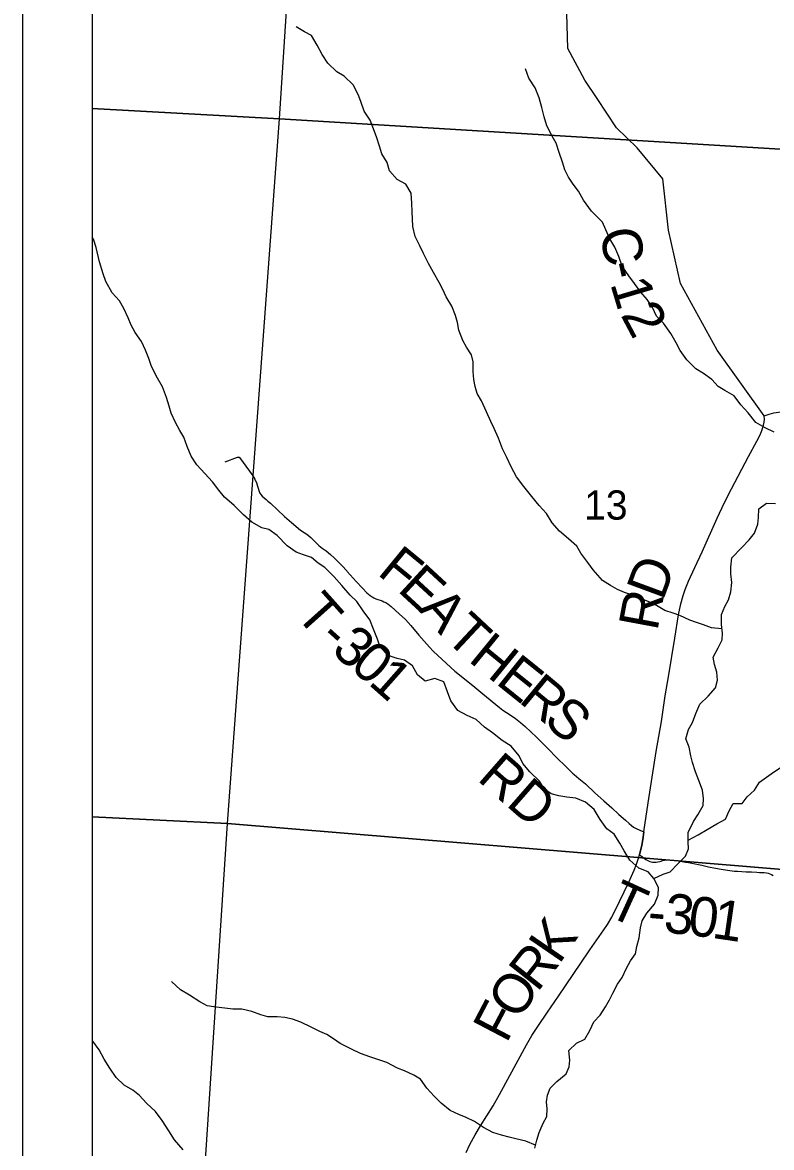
# Model space of a CAD drawing. Extents: x 0 to 34, y 0 to 22.
# Drawn here: x 2 to 3.074, y 15.5 to 17.112 of the extents above; entities that cross this region are included whole.
import ezdxf

# ---------------------------------------------------------------- set-up
doc = ezdxf.new("R2010")
doc.units = 0
for name, color, linetype in [('GM_X_Corporation', 7, 'Continuous'), ('GM_X_County_Road', 7, 'Continuous'), ('GM_X_County_Road_Text', 7, 'Continuous'), ('GM_X_Major_River', 7, 'Continuous'), ('GM_X_Minor_River', 7, 'Continuous'), ('GM_X_Section_Text', 7, 'Continuous'), ('GM_X_Township_Road', 7, 'Continuous'), ('GM_X_Township_Road_Text', 7, 'Continuous'), ('SH_Data', 7, 'Continuous')]:
    doc.layers.add(name, color=color, linetype=linetype)

msp = doc.modelspace()

# ---------------------------------------------------------------- linework, layer by layer
at = {"layer": 'GM_X_Corporation'}
for points in [[(2.1, 19.0816), (2.1, 14.1), (3.1902, 14.1), (3.1919, 14.1255), (3.2339, 14.7735), (3.2844, 15.554), (3.3059, 15.8844), (3.3516, 16.5898), (3.3951, 17.2616), (3.507, 18.9883), (2.9513, 19.0267), (2.509, 19.0572), (2.4972, 19.0545), (2.4649, 19.0567)], [(2.1, 18.0323), (2.1, 16.9887), (2.3682, 16.9741), (2.436, 18.0137)], [(2.436, 18.0137), (3.4457, 17.9455), (3.3779, 16.9127), (2.3682, 16.9741)], [(2.1, 16.9887), (2.1, 15.9736), (2.2939, 15.964), (2.3682, 16.9741)], [(3.3779, 16.9127), (3.31, 15.8916), (3.3089, 15.8803), (2.2939, 15.964), (2.3682, 16.9741)], [(2.1, 15.9736), (2.1, 14.9482), (2.2272, 14.9411), (2.2939, 15.964)], [(2.2939, 15.964), (3.3089, 15.8803), (3.2437, 14.8797), (2.2272, 14.9411)]]:
    msp.add_lwpolyline(points, close=True, dxfattribs=at)
at = {"layer": 'GM_X_County_Road'}
for points in [[(3.0632, 16.5485), (2.996, 16.6425), (2.9433, 16.738), (2.926, 16.8142), (2.9178, 16.8878), (2.8812, 16.9325), (2.8515, 16.9612), (2.8237, 17.0029), (2.8062, 17.0294), (2.7818, 17.0745), (2.777, 17.2417)], [(3.0632, 16.5485), (3.0704, 16.5509), (3.077, 16.5524), (3.0838, 16.5537), (3.0931, 16.5548), (3.1025, 16.5553), (3.1119, 16.5551), (3.1274, 16.5537), (3.1459, 16.552), (3.1583, 16.5514), (3.1706, 16.5515), (3.186, 16.5523), (3.2138, 16.5548), (3.2694, 16.5609), (3.2847, 16.5631), (3.2938, 16.5648), (3.3027, 16.5672), (3.3085, 16.5693), (3.3226, 16.5756), (3.3563, 16.5915), (3.3576, 16.592), (3.363, 16.5943)], [(2.8907, 15.9522), (2.8967, 15.9938), (2.9084, 16.0673), (2.9158, 16.1102), (2.9215, 16.147), (2.9262, 16.1745), (2.935, 16.2297), (2.9406, 16.2634), (2.9438, 16.2787), (2.947, 16.2907), (2.95, 16.2996), (2.9546, 16.3112), (2.9637, 16.3309), (2.9744, 16.3533), (2.9959, 16.4015), (3.0065, 16.424), (3.0162, 16.4435), (3.0408, 16.4901), (3.0529, 16.5118), (3.057, 16.52), (3.0595, 16.5257), (3.0615, 16.5314), (3.0623, 16.5347), (3.0632, 16.539), (3.0635, 16.5436), (3.0632, 16.5485)], [(2.8844, 15.9194), (2.8856, 15.9235), (2.8876, 15.9326), (2.8897, 15.9447), (2.8907, 15.9522)], [(2.636, 15.4929), (2.6413, 15.5042), (2.6487, 15.518), (2.6566, 15.5312), (2.6747, 15.5598), (2.6839, 15.5759), (2.7224, 15.6468), (2.7302, 15.6603), (2.7385, 15.6734), (2.7525, 15.694), (2.7685, 15.7169), (2.8112, 15.7801), (2.8133, 15.7832), (2.8335, 15.8116), (2.8386, 15.8193), (2.8446, 15.8301), (2.8557, 15.8523), (2.869, 15.8803), (2.8766, 15.8973), (2.8801, 15.9059), (2.8831, 15.9146), (2.8844, 15.9194)]]:
    msp.add_lwpolyline(points, dxfattribs=at)
at = {"layer": 'GM_X_Major_River'}
for points in [[(2.9647, 16.0382), (2.9605, 16.0514), (2.9582, 16.0613), (2.9555, 16.0734), (2.9509, 16.0855), (2.9547, 16.0988), (2.9603, 16.1087), (2.9652, 16.1216), (2.9708, 16.1352), (2.9829, 16.1467), (2.9934, 16.1588), (2.9961, 16.1695), (2.9953, 16.1808), (2.9918, 16.1922), (2.9899, 16.2024), (2.9974, 16.2157), (3.003, 16.2275), (3.0034, 16.2369), (3.0018, 16.2491), (3.0022, 16.2635), (3.007, 16.2749), (3.0119, 16.2847), (3.0153, 16.2961), (3.0168, 16.3094), (3.0156, 16.3219), (3.0155, 16.3314), (3.017, 16.3446), (3.0306, 16.3591), (3.0415, 16.3705), (3.0494, 16.38), (3.0539, 16.3933), (3.055, 16.4028), (3.0554, 16.4149), (3.0663, 16.4233), (3.0792, 16.4226)], [(2.7342, 15.499), (2.7372, 15.5104), (2.7406, 15.5214), (2.7466, 15.5347), (2.7515, 15.5442), (2.7522, 15.5552), (2.751, 15.5654), (2.7525, 15.5749), (2.7563, 15.5851), (2.7661, 15.5947), (2.7793, 15.6053), (2.7838, 15.6156), (2.7845, 15.6251), (2.7833, 15.6387), (2.7943, 15.6494), (2.806, 15.6551), (2.8135, 15.6676), (2.8191, 15.6798), (2.8282, 15.6897), (2.8357, 15.7015), (2.8414, 15.7117), (2.8462, 15.7212), (2.853, 15.7341), (2.8598, 15.7436), (2.8658, 15.7569), (2.8718, 15.7672), (2.8786, 15.7775), (2.8808, 15.7881), (2.8842, 15.8002), (2.886, 15.8146), (2.8883, 15.8245), (2.895, 15.8359), (2.906, 15.8488), (2.9112, 15.8617), (2.9116, 15.8723), (2.9051, 15.8856), (2.9183, 15.8917), (2.9285, 15.8948), (2.9394, 15.9066), (2.9504, 15.9176), (2.9549, 15.9279), (2.9541, 15.9381), (2.9544, 15.9514), (2.9619, 15.9669), (2.968, 15.9768), (2.9759, 15.9901), (2.9762, 16), (2.975, 16.0121), (2.9697, 16.0257), (2.9647, 16.0382)]]:
    msp.add_lwpolyline(points, dxfattribs=at)
at = {"layer": 'GM_X_Minor_River'}
for p, q in [((2.4043, 17.0987), (2.3925, 17.1055)), ((2.4145, 17.0931), (2.4043, 17.0987)), ((2.4225, 17.0795), (2.4145, 17.0931)), ((2.4294, 17.0662), (2.4225, 17.0795)), ((2.4377, 17.0538), (2.4294, 17.0662)), ((2.4506, 17.0413), (2.4377, 17.0538)), ((2.4613, 17.0349), (2.4506, 17.0413)), ((2.7258, 17.0323), (2.7209, 17.0456)), ((2.4742, 17.0228), (2.4613, 17.0349)), ((2.481, 17.0085), (2.4742, 17.0228)), ((2.735, 17.0183), (2.7258, 17.0323)), ((2.4852, 16.9986), (2.481, 17.0085)), ((2.7407, 17.004), (2.735, 17.0183)), ((2.4898, 16.985), (2.4852, 16.9986)), ((2.7445, 16.9903), (2.7407, 17.004)), ((2.7476, 16.9767), (2.7445, 16.9903)), ((2.4986, 16.9718), (2.4898, 16.985)), ((2.7518, 16.9638), (2.7476, 16.9767)), ((2.5024, 16.962), (2.4986, 16.9718)), ((2.5074, 16.948), (2.5024, 16.962)), ((2.7594, 16.9491), (2.7518, 16.9638)), ((2.512, 16.9347), (2.5074, 16.948)), ((2.7648, 16.9389), (2.7594, 16.9491)), ((2.515, 16.9237), (2.512, 16.9347)), ((2.7694, 16.9256), (2.7648, 16.9389)), ((2.5226, 16.9113), (2.515, 16.9237)), ((2.5261, 16.8995), (2.5226, 16.9113)), ((2.7739, 16.912), (2.7694, 16.9256)), ((2.7774, 16.901), (2.7739, 16.912)), ((2.5371, 16.8871), (2.5261, 16.8995)), ((2.7827, 16.8905), (2.7774, 16.901)), ((2.5496, 16.8803), (2.5371, 16.8871)), ((2.5572, 16.8675), (2.5496, 16.8803)), ((2.7896, 16.8802), (2.7827, 16.8905)), ((2.7968, 16.87), (2.7896, 16.8802)), ((2.558, 16.8531), (2.5572, 16.8675)), ((2.804, 16.8572), (2.7968, 16.87)), ((2.5588, 16.8406), (2.558, 16.8531)), ((2.8158, 16.8417), (2.804, 16.8572)), ((2.5593, 16.8307), (2.5588, 16.8406)), ((2.5597, 16.8197), (2.5593, 16.8307)), ((2.8314, 16.8259), (2.8158, 16.8417)), ((2.5631, 16.8053), (2.5597, 16.8197)), ((2.836, 16.8149), (2.8314, 16.8259)), ((2.8421, 16.8017), (2.836, 16.8149)), ((2.5696, 16.7917), (2.5631, 16.8053)), ((2.8493, 16.7899), (2.8421, 16.8017)), ((2.5746, 16.7811), (2.5696, 16.7917)), ((2.5822, 16.7668), (2.5746, 16.7811)), ((2.855, 16.7767), (2.8493, 16.7899)), ((2.589, 16.7535), (2.5822, 16.7668)), ((2.8596, 16.7627), (2.855, 16.7767)), ((2.5974, 16.7392), (2.589, 16.7535)), ((2.8691, 16.7487), (2.8596, 16.7627)), ((2.8775, 16.7378), (2.8691, 16.7487)), ((2.6024, 16.7293), (2.5974, 16.7392)), ((2.8866, 16.7257), (2.8775, 16.7378)), ((2.6073, 16.7187), (2.6024, 16.7293)), ((2.6153, 16.7055), (2.6073, 16.7187)), ((2.8954, 16.7151), (2.8866, 16.7257)), ((2.6207, 16.6923), (2.6153, 16.7055)), ((2.903, 16.7034), (2.8954, 16.7151)), ((2.9087, 16.6909), (2.903, 16.7034)), ((2.6234, 16.6821), (2.6207, 16.6923)), ((2.9189, 16.6811), (2.9087, 16.6909)), ((2.6257, 16.6711), (2.6234, 16.6821)), ((2.631, 16.6563), (2.6257, 16.6711)), ((2.9296, 16.6664), (2.9189, 16.6811)), ((2.6367, 16.6465), (2.631, 16.6563)), ((2.9368, 16.6531), (2.9296, 16.6664)), ((2.9429, 16.6418), (2.9368, 16.6531)), ((2.6436, 16.6355), (2.6367, 16.6465)), ((2.9521, 16.6286), (2.9429, 16.6418)), ((2.6459, 16.6257), (2.6436, 16.6355)), ((2.6459, 16.6117), (2.6459, 16.6257)), ((2.965, 16.6157), (2.9521, 16.6286)), ((2.6471, 16.6003), (2.6459, 16.6117)), ((2.9764, 16.609), (2.965, 16.6157)), ((2.9881, 16.6003), (2.9764, 16.609)), ((2.6487, 16.5905), (2.6471, 16.6003)), ((2.6517, 16.5802), (2.6487, 16.5905)), ((2.9972, 16.5901), (2.9881, 16.6003)), ((3.0067, 16.5845), (2.9972, 16.5901)), ((2.6582, 16.5697), (2.6517, 16.5802)), ((3.02, 16.577), (3.0067, 16.5845)), ((3.0299, 16.5641), (3.02, 16.577)), ((2.6651, 16.5538), (2.6582, 16.5697)), ((3.0401, 16.5524), (3.0299, 16.5641)), ((2.6712, 16.5402), (2.6651, 16.5538)), ((2.6761, 16.5303), (2.6712, 16.5402)), ((3.0512, 16.5388), (3.0401, 16.5524)), ((2.6822, 16.5163), (2.6761, 16.5303)), ((3.0644, 16.5309), (3.0512, 16.5388)), ((3.0777, 16.5249), (3.0644, 16.5309)), ((2.6883, 16.5012), (2.6822, 16.5163)), ((2.6944, 16.4887), (2.6883, 16.5012)), ((2.7005, 16.4751), (2.6944, 16.4887)), ((2.7082, 16.4607), (2.7005, 16.4751)), ((2.7188, 16.4471), (2.7082, 16.4607)), ((2.7302, 16.4328), (2.7188, 16.4471)), ((2.7405, 16.4199), (2.7302, 16.4328)), ((2.7511, 16.4082), (2.7405, 16.4199)), ((2.7591, 16.395), (2.7511, 16.4082)), ((2.7697, 16.3829), (2.7591, 16.395)), ((2.7826, 16.372), (2.7697, 16.3829)), ((2.7944, 16.3615), (2.7826, 16.372)), ((2.8005, 16.3516), (2.7944, 16.3615)), ((2.8104, 16.338), (2.8005, 16.3516)), ((2.818, 16.3278), (2.8104, 16.338)), ((2.8313, 16.3124), (2.818, 16.3278)), ((2.8431, 16.3052), (2.8313, 16.3124)), ((2.8529, 16.2996), (2.8431, 16.3052)), ((2.8631, 16.2951), (2.8529, 16.2996)), ((2.8764, 16.291), (2.8631, 16.2951)), ((2.8859, 16.2864), (2.8764, 16.291)), ((2.8995, 16.2812), (2.8859, 16.2864)), ((2.909, 16.2767), (2.8995, 16.2812)), ((2.9208, 16.2695), (2.909, 16.2767)), ((2.9325, 16.2654), (2.9208, 16.2695)), ((2.9424, 16.2624), (2.9325, 16.2654)), ((2.9568, 16.2553), (2.9424, 16.2624)), ((2.9662, 16.2523), (2.9568, 16.2553)), ((2.9761, 16.249), (2.9662, 16.2523)), ((2.9878, 16.2445), (2.9761, 16.249)), ((3.0026, 16.243), (2.9878, 16.2445)), ((3.073, 16.0353), (3.0881, 16.0456)), ((3.0492, 16.012), (3.0567, 16.0234)), ((3.0567, 16.0234), (3.073, 16.0353)), ((3.0387, 16.0025), (3.0492, 16.012)), ((3.013, 15.9823), (3.0186, 15.9926)), ((3.0186, 15.9926), (3.0315, 15.9926)), ((3.0315, 15.9926), (3.0387, 16.0025)), ((3.0077, 15.9706), (3.013, 15.9823)), ((2.9817, 15.9557), (2.9953, 15.9637)), ((2.9953, 15.9637), (3.0077, 15.9706)), ((2.9541, 15.9401), (2.9688, 15.948)), ((2.9688, 15.948), (2.9817, 15.9557)), ((2.2263, 15.726), (2.2137, 15.7377)), ((2.2396, 15.7181), (2.2263, 15.726)), ((2.254, 15.7087), (2.2396, 15.7181)), ((2.2646, 15.7027), (2.254, 15.7087)), ((2.2744, 15.7016), (2.2646, 15.7027)), ((2.3017, 15.6979), (2.2744, 15.7016)), ((2.3142, 15.698), (2.3017, 15.6979)), ((2.3286, 15.695), (2.3142, 15.698)), ((2.3415, 15.6898), (2.3286, 15.695)), ((2.3517, 15.6872), (2.3415, 15.6898)), ((2.3653, 15.6872), (2.3517, 15.6872)), ((2.3759, 15.6861), (2.3653, 15.6872)), ((2.3869, 15.6839), (2.3759, 15.6861)), ((2.399, 15.6794), (2.3869, 15.6839)), ((2.4138, 15.6723), (2.399, 15.6794)), ((2.4263, 15.6663), (2.4138, 15.6723)), ((2.1009, 15.6523), (2.1, 15.6534)), ((2.4362, 15.6618), (2.4263, 15.6663)), ((2.446, 15.6558), (2.4362, 15.6618)), ((2.4555, 15.649), (2.446, 15.6558)), ((2.11, 15.6398), (2.1009, 15.6523)), ((2.1172, 15.6266), (2.11, 15.6398)), ((2.4718, 15.6407), (2.4555, 15.649)), ((2.4843, 15.6347), (2.4718, 15.6407)), ((2.1252, 15.6134), (2.1172, 15.6266)), ((2.498, 15.6298), (2.4843, 15.6347)), ((2.5222, 15.6216), (2.498, 15.6298)), ((2.5378, 15.6137), (2.5222, 15.6216)), ((2.1344, 15.6002), (2.1252, 15.6134)), ((2.5476, 15.61), (2.5378, 15.6137)), ((2.5609, 15.6036), (2.5476, 15.61)), ((2.1458, 15.5892), (2.1344, 15.6002)), ((2.1583, 15.5821), (2.1458, 15.5892)), ((2.5704, 15.5979), (2.5609, 15.6036)), ((2.5795, 15.5851), (2.5704, 15.5979)), ((2.1678, 15.5745), (2.1583, 15.5821)), ((2.178, 15.5636), (2.1678, 15.5745)), ((2.5902, 15.5734), (2.5795, 15.5851)), ((2.6, 15.5636), (2.5902, 15.5734)), ((2.1906, 15.5515), (2.178, 15.5636)), ((2.6133, 15.553), (2.6, 15.5636)), ((2.2001, 15.5387), (2.1906, 15.5515)), ((2.6254, 15.5474), (2.6133, 15.553)), ((2.6361, 15.5429), (2.6254, 15.5474)), ((2.6478, 15.5373), (2.6361, 15.5429)), ((2.2096, 15.5239), (2.2001, 15.5387)), ((2.218, 15.5107), (2.2096, 15.5239)), ((2.6607, 15.5286), (2.6478, 15.5373)), ((2.674, 15.5215), (2.6607, 15.5286)), ((2.2305, 15.4964), (2.218, 15.5107)), ((2.6865, 15.5177), (2.674, 15.5215)), ((2.6978, 15.5148), (2.6865, 15.5177)), ((2.7073, 15.5122), (2.6978, 15.5148)), ((2.7213, 15.5088), (2.7073, 15.5122)), ((2.7354, 15.5035), (2.7213, 15.5088))]:
    msp.add_line(p, q, dxfattribs=at)
msp.add_lwpolyline([(2.9051, 15.8856), (2.8967, 15.895), (2.8835, 15.9003), (2.8705, 15.9116), (2.8626, 15.9252), (2.8561, 15.9361), (2.8481, 15.949), (2.8378, 15.9565), (2.828, 15.9697), (2.8196, 15.9841), (2.8071, 15.9947), (2.793, 16.0007), (2.7805, 16.0017), (2.7688, 16.0036), (2.7578, 16.0069), (2.7483, 16.0133), (2.7411, 16.0247), (2.7274, 16.0383), (2.7172, 16.0503), (2.7118, 16.0609), (2.7004, 16.0749), (2.6875, 16.0832), (2.6739, 16.0941), (2.6621, 16.1024), (2.6503, 16.1133), (2.6374, 16.119), (2.6242, 16.1261), (2.6139, 16.1397), (2.6093, 16.1526), (2.604, 16.1673), (2.5911, 16.1718), (2.5771, 16.1683), (2.5661, 16.1774), (2.5592, 16.1902), (2.5475, 16.1981), (2.5369, 16.2007), (2.524, 16.2049), (2.5126, 16.2166), (2.5091, 16.2283), (2.5034, 16.2427), (2.4981, 16.2559), (2.4882, 16.2687), (2.4794, 16.2823), (2.4695, 16.2914), (2.4578, 16.305), (2.4467, 16.3178), (2.4335, 16.331), (2.424, 16.3374), (2.4141, 16.3453), (2.4027, 16.3491), (2.3921, 16.3528), (2.3792, 16.3619), (2.3652, 16.377), (2.353, 16.3856), (2.3432, 16.3879), (2.3288, 16.3961), (2.317, 16.4063), (2.3033, 16.4199), (2.2897, 16.4319), (2.2813, 16.4418), (2.2726, 16.4535), (2.2615, 16.4659), (2.2501, 16.478), (2.2418, 16.4905), (2.236, 16.5045), (2.2311, 16.5177), (2.2257, 16.5275), (2.2193, 16.5389), (2.2132, 16.5521), (2.2101, 16.5623), (2.2066, 16.5748), (2.2009, 16.59), (2.1914, 16.6058), (2.1845, 16.6202), (2.1811, 16.6304), (2.1765, 16.6422), (2.1704, 16.6546), (2.1617, 16.6679), (2.1559, 16.6784), (2.1517, 16.6887), (2.1453, 16.7019), (2.1392, 16.7129), (2.1285, 16.7246), (2.1194, 16.7408), (2.1156, 16.7518), (2.1102, 16.7688), (2.1056, 16.7893), (2.1018, 16.8014), (2.1, 16.8038)], dxfattribs=at)
at = {"layer": 'GM_X_Township_Road'}
for points in [[(2.2905, 16.4823), (2.3083, 16.4892), (2.3091, 16.4893), (2.3099, 16.4893), (2.3106, 16.4889), (2.3109, 16.4885), (2.3254, 16.4691), (2.3301, 16.4625), (2.3332, 16.4576), (2.3354, 16.4523), (2.3372, 16.4463), (2.3392, 16.44), (2.3403, 16.4377), (2.3415, 16.4356), (2.3435, 16.4331), (2.3462, 16.4306), (2.3493, 16.4282), (2.3518, 16.4261), (2.3554, 16.4232), (2.3757, 16.404), (2.3856, 16.3956), (2.3986, 16.3847), (2.4038, 16.3809), (2.4074, 16.3786), (2.4103, 16.3765), (2.4133, 16.3741), (2.4154, 16.372), (2.4195, 16.3676), (2.4247, 16.3627), (2.4298, 16.3589), (2.4353, 16.3547), (2.4413, 16.3497), (2.4471, 16.3443), (2.4527, 16.3391), (2.4584, 16.3336), (2.4648, 16.3261), (2.4655, 16.3254)], [(2.4655, 16.3254), (2.4783, 16.3107), (2.4873, 16.3015), (2.4938, 16.2949), (2.4985, 16.2909), (2.5011, 16.2891), (2.5037, 16.2876), (2.5066, 16.2863), (2.5154, 16.2832), (2.5182, 16.282), (2.521, 16.2807), (2.5236, 16.279), (2.5284, 16.2751), (2.5399, 16.2648), (2.5488, 16.2563), (2.5568, 16.2477), (2.5682, 16.234), (2.5833, 16.2167), (2.5885, 16.2113), (2.6079, 16.1932), (2.6198, 16.1826), (2.6457, 16.1618), (2.6598, 16.15), (2.6836, 16.1305), (2.6886, 16.1268), (2.6989, 16.1199), (2.7067, 16.1145), (2.7139, 16.1089), (2.7205, 16.1031), (2.7369, 16.0879), (2.7522, 16.0727), (2.767, 16.0571), (2.778, 16.0466), (2.7886, 16.0364), (2.791, 16.0343)], [(2.791, 16.0343), (2.7974, 16.0286), (2.8069, 16.0209), (2.8204, 16.0083), (2.8334, 15.9966), (2.8448, 15.9865), (2.855, 15.977), (2.8644, 15.9688), (2.8697, 15.9641), (2.8729, 15.9613), (2.876, 15.9589), (2.8796, 15.9569), (2.8848, 15.9545), (2.8907, 15.9522)], [(2.8907, 15.9522), (2.8897, 15.9447), (2.8876, 15.9326), (2.8856, 15.9235), (2.8844, 15.9194)], [(2.8844, 15.9194), (2.8875, 15.9172), (2.8935, 15.9128), (2.8956, 15.9116), (2.8974, 15.9106), (2.8993, 15.9098), (2.9012, 15.9093), (2.9032, 15.909), (2.9057, 15.9089), (2.9083, 15.909), (2.9109, 15.9093), (2.9138, 15.9098), (2.9155, 15.9102), (2.9185, 15.9115), (2.9202, 15.9118), (2.922, 15.9119), (2.9244, 15.912), (2.9278, 15.9119), (2.9316, 15.9116), (2.9363, 15.9112), (2.941, 15.9105), (2.9502, 15.909), (2.9548, 15.9081), (2.9665, 15.9058), (2.9739, 15.9043), (2.9836, 15.9023), (2.9932, 15.9004), (3.0015, 15.8988), (3.0108, 15.8971), (3.0139, 15.8967), (3.0171, 15.8963), (3.0205, 15.896), (3.0251, 15.8957), (3.0313, 15.8952), (3.0375, 15.8949), (3.0449, 15.8948), (3.0527, 15.8943), (3.0564, 15.894), (3.06, 15.8939), (3.0633, 15.8938), (3.0664, 15.8936), (3.0689, 15.8932), (3.0712, 15.8921), (3.0736, 15.8909), (3.076, 15.8899)]]:
    msp.add_lwpolyline(points, dxfattribs=at)
at = {"layer": 'SH_Data'}
for p, q in [((2, 21), (2, 14)), ((2.1, 20.9), (2.1, 14.1))]:
    msp.add_line(p, q, dxfattribs=at)

# ---------------------------------------------------------------- texts
at = {"layer": 'GM_X_County_Road_Text'}
for s, rotation, p in [('C', 280.0982, (2.8273, 16.8135)), ('-', 282.3397, (2.836, 16.7652)), ('1', 286.6415, (2.8422, 16.7379)), ('2', 297.9166, (2.8568, 16.6931)), ('D', 69.6951, (2.9179, 16.2822)), ('R', 79.4257, (2.91, 16.2388)), ('K', 55.574, (2.7692, 15.7612)), ('R', 51.6803, (2.7378, 15.7212)), ('O', 56.3221, (2.7108, 15.6806)), ('F', 62.3725, (2.6938, 15.648))]:
    msp.add_text(s, height=0.0568, rotation=rotation, dxfattribs=at).set_placement(p)
at = {"layer": 'GM_X_Section_Text'}
msp.add_text('13', height=0.04186, rotation=0, dxfattribs=at).set_placement((2.8051, 16.3996))
at = {"layer": 'GM_X_Township_Road_Text'}
for s, height, rotation, p in [('F', 0.0568, 320.6033, (2.5071, 16.3219)), ('E', 0.0568, 317.3463, (2.536, 16.2982)), ('T', 0.0568, 311.7375, (2.3894, 16.2632)), ('A', 0.0568, 311.9772, (2.5663, 16.2704)), ('T', 0.0568, 316.9085, (2.6035, 16.2294)), ('-', 0.0568, 317.9692, (2.4225, 16.2267)), ('3', 0.0568, 319.5045, (2.4411, 16.21)), ('H', 0.0568, 320.703, (2.6376, 16.1977)), ('0', 0.0568, 319.598, (2.4677, 16.1872)), ('E', 0.0568, 321.2837, (2.6768, 16.1656)), ('1', 0.0568, 318.5164, (2.4942, 16.1647)), ('R', 0.0568, 320.3563, (2.7098, 16.1392)), ('S', 0.0568, 317.8637, (2.7452, 16.1098)), ('RD', 0.05682, 318.8291, (2.6503, 16.0271)), ('T', 0.0568, 335.4784, (2.8358, 15.8334)), ('3', 0.0568, 353.7851, (2.9178, 15.8084)), ('0', 0.0568, 353.0351, (2.9524, 15.8047)), ('1', 0.0568, 351.6911, (2.9868, 15.8005)), ('-', 0.0568, 355.1736, (2.8949, 15.8104))]:
    msp.add_text(s, height=height, rotation=rotation, dxfattribs=at).set_placement(p)

doc.saveas('drawing.dxf')
